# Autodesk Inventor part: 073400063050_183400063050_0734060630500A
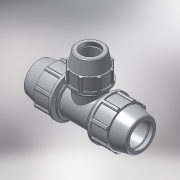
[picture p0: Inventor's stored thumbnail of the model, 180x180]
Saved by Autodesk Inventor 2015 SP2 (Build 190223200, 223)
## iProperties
Created: 2017-02
Part Number: 073400063050_183400063050_0734060630500A
Material: PVC-Piping
Description: PLASSON REDUCING TEE 63-50-63
Document SubType Name: Modeling
Designer: KIM
Mass: 92.6774 g
Surface Area: 199.44 cm^2
Volume: 66.1981 cm^3
Density: 1.4 g/cm^3
Appearance: Smooth - White
Author: Кирилл
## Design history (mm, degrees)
derived "07340.ipt"
feature "Solid1::07340.ipt"
feature "Solid2::07340.ipt"
tag "TaggingFeature1"
body "Solid1"
other parameters: "d2" = 63, "d4" = 11.45833, "d5" = 38.5, "d7" = 113, "d11" = 4.58333, "d13" = 120 deg, "d14" = 81.9, "d15" = 12 deg, "d16" = 98.31, "d18" = 3.15, "d19" = 35 deg, "d20" = 17.5 deg, "d21" = 105.09, "d23" = 0, "d25" = 360 deg, "d27" = 2.26, "d33" = 1.26, "d42" = 49.5, "d43" = 3.39, "d46" = 1.89, "d67" = 84.75, "d77" = 96, "d78" = 12 deg, "d79" = 132, "d80" = 120 deg, "d82" = 11, "d87" = 4.4, "d89" = 33, "d90" = 39.6, "d96" = 22.91667, "d98" = 89.28, "d99" = 35 deg, "d100" = 17.5 deg, "d102" = 0, "d103" = 1.92, "d107" = 360 deg, "d109" = 1.5, "d112" = 2.5, "d113" = 6.4, "d114" = 0, "d117" = 275, "d118" = 83.52, "d126" = 56.7, "d131" = 5.28, "d132" = 45, "d133" = 93, "d135" = 0, "d138" = 5.5, "d143" = 0, "d148" = 72, "d168" = 56.7, "d170" = 0, "d173" = 0, "d175" = 0, "d176" = 6.4, "d177" = 0, "d_" = 63, "E_" = 113, "A_" = 132, "E_1" = 96, "l_1" = 93, "H_" = 275
